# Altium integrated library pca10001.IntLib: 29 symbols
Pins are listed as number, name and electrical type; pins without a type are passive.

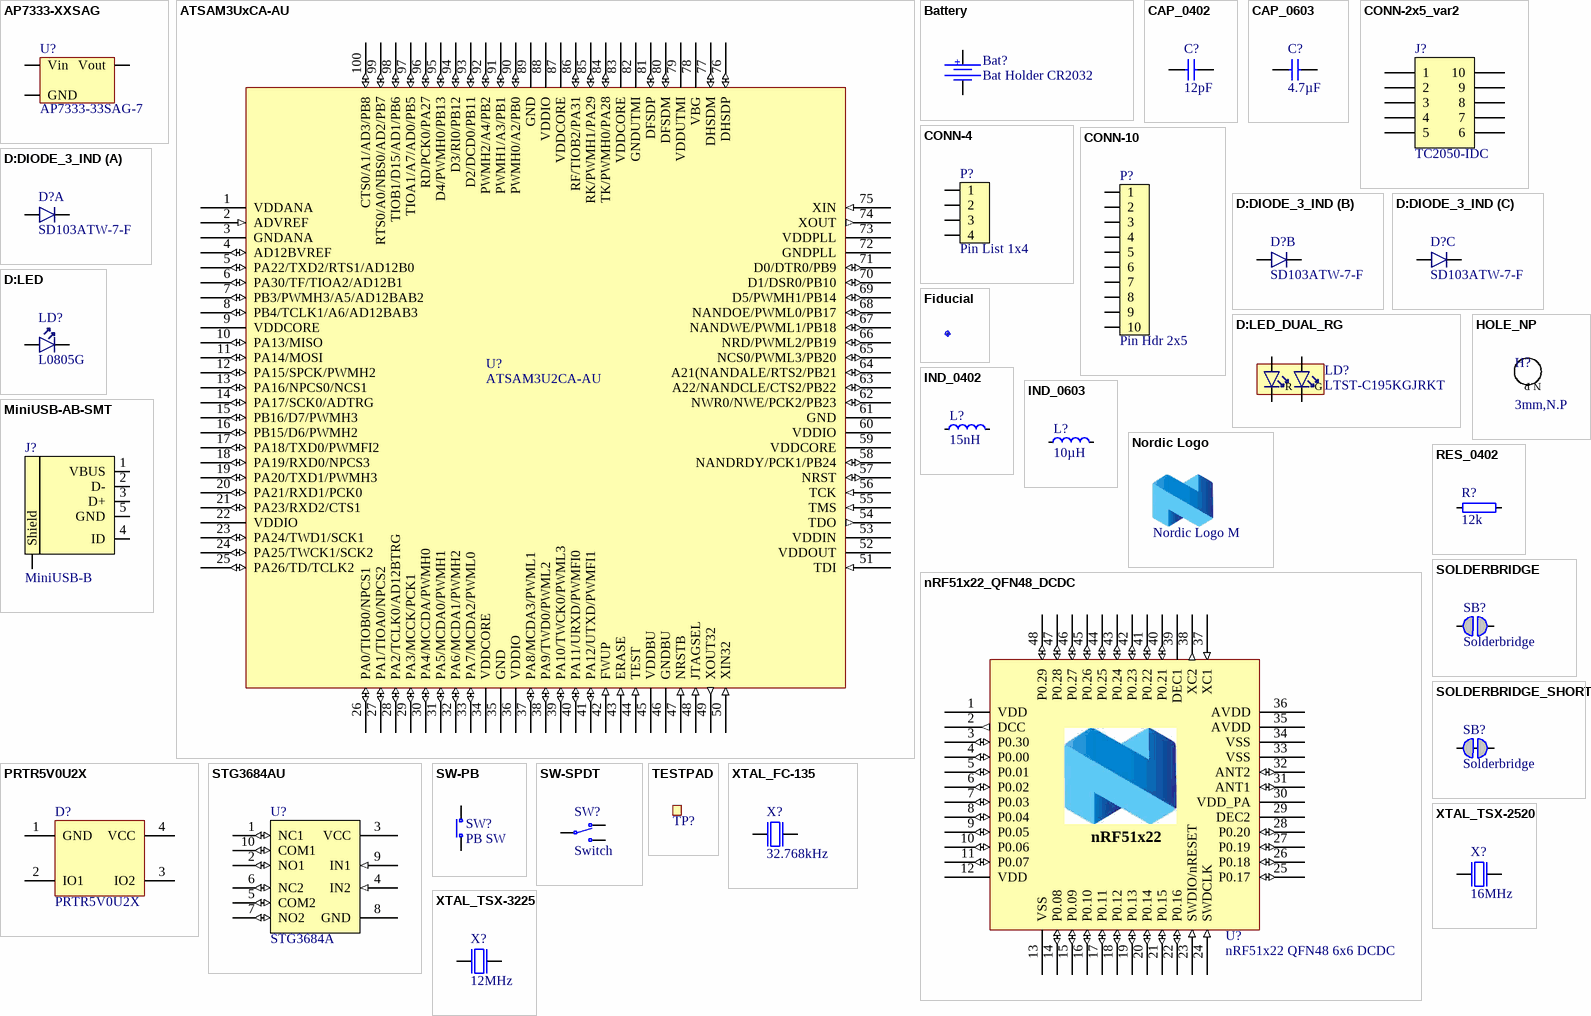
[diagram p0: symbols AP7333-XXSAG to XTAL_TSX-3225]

## AP7333-XXSAG
designator U?, comment AP7333-33SAG-7
300mA, Low Quiescent Current, Fast Transient Low Dropout Linear Regulator; Manufacturer: Diodes Incorporated; Artikkelnr Noca: 17039216
footprint SOT-23A
pins: 1 Vin, 2 Vout, 3 GND

## ATSAM3UxCA-AU
designator U?, comment ATSAM3U2CA-AU
IC MCU 32bit 128kB flash 100LQFP; Manufacturer: Atmel; 2nd source part number: 184-1662; Artikkelnr Noca: 15019073
footprint TSQFP50P1600X1600X160-100N
pins: 1 VDDANA (power), 2 ADVREF (in), 3 GNDANA (power), 4 AD12BVREF (io), 5 PA22/TXD2/RTS1/AD12B0 (io), 6 PA30/TF/TIOA2/AD12B1 (io), 7 PB3/PWMH3/A5/AD12BAB2 (io), 8 PB4/TCLK1/A6/AD12BAB3 (io), 9 VDDCORE (power), 10 PA13/MISO (io), 11 PA14/MOSI (io), 12 PA15/SPCK/PWMH2 (io), 13 PA16/NPCS0/NCS1 (io), 14 PA17/SCK0/ADTRG (io), 15 PB16/D7/PWMH3 (io), 16 PB15/D6/PWMH2 (io), 17 PA18/TXD0/PWMFI2 (io), 18 PA19/RXD0/NPCS3 (io), 19 PA20/TXD1/PWMH3 (io), 20 PA21/RXD1/PCK0 (io), 21 PA23/RXD2/CTS1 (io), 22 VDDIO (power), 23 PA24/TWD1/SCK1 (io), 24 PA25/TWCK1/SCK2 (io), 25 PA26/TD/TCLK2 (io), 26 PA0/TIOB0/NPCS1 (io), 27 PA1/TIOA0/NPCS2 (io), 28 PA2/TCLK0/AD12BTRG (io), 29 PA3/MCCK/PCK1 (io), 30 PA4/MCCDA/PWMH0 (io), 31 PA5/MCDA0/PWMH1 (io), 32 PA6/MCDA1/PWMH2 (io), 33 PA7/MCDA2/PWML0 (io), 34 VDDCORE (power), 35 GND (power), 36 VDDIO (power), 37 PA8/MCDA3/PWML1 (io), 38 PA9/TWD0/PWML2 (io), 39 PA10/TWCK0/PWML3 (io), 40 PA11/URXD/PWMFI0 (io), 41 PA12/UTXD/PWMFI1 (io), 42 FWUP (in), 43 ERASE (in), 44 TEST (in), 45 VDDBU (power), 46 GNDBU (power), 47 NRSTB (in), 48 JTAGSEL (in), 49 XOUT32 (out), 50 XIN32 (in), 51 TDI (in), 52 VDDOUT (power), 53 VDDIN (power), 54 TDO (out), 55 TMS (in), 56 TCK (in), 57 NRST (io), 58 NANDRDY/PCK1/PB24 (io), 59 VDDCORE (power), 60 VDDIO (power), 61 GND (power), 62 NWR0/NWE/PCK2/PB23 (io), 63 A22/NANDCLE/CTS2/PB22 (io), 64 A21(NANDALE/RTS2/PB21 (io), 65 NCS0/PWML3/PB20 (io), 66 NRD/PWML2/PB19 (io), 67 NANDWE/PWML1/PB18 (io), 68 NANDOE/PWML0/PB17 (io), 69 D5/PWMH1/PB14 (io), 70 D1/DSR0/PB10 (io), 71 D0/DTR0/PB9 (io), 72 GNDPLL (power), 73 VDDPLL (power), 74 XOUT (out), 75 XIN (in), 76 DHSDP (io), 77 DHSDM (io), 78 VBG (power), 79 VDDUTMI (power), 80 DFSDM (io), 81 DFSDP (io), 82 GNDUTMI (power), 83 VDDCORE (power), 84 TK/PWMH0/PA28 (io), 85 RK/PWMH1/PA29 (io), 86 RF/TIOB2/PA31 (io), 87 VDDCORE (power), 88 VDDIO (power), 89 GND (power), 90 PWMH0/A2/PB0 (io), 91 PWMH1/A3/PB1 (io), 92 PWMH2/A4/PB2 (io), 93 D2/DCD0/PB11 (io), 94 D3/RI0/PB12 (io), 95 D4/PWMH0/PB13 (io), 96 RD/PCK0/PA27 (io), 97 TIOA1/A7/AD0/PB5 (io), 98 TIOB1/D15/AD1/PB6 (io), 99 RTS0/A0/NBS0/AD2/PB7 (io), 100 CTS0/A1/AD3/PB8 (io)

## Battery
designator Bat?, comment Bat Holder CR2032
Bat Holder CR2032 SMD; Manufacturer: Keystone; Manufacturer Part Number: 3002; 2nd source part number: 69-525-27; Artikkelnr Noca: 34019038
footprint CR2032_HOLDER_SMD
pins: 1, 2

## CAP_0402
designator C?, comment 12pF
Capacitor, NP0, ±2%; Part Number: C0402-12p; Note: 50V; Artikkelnr Noca: 20029159
footprint CAPC1005X04L
pins: 1, 2

## CAP_0603
designator C?, comment 4.7µF
Capacitor, X5R, ±10%; Part Number: C0603-4µ7; Note: 6.3V; Artikkelnr Noca: 20069060
footprint CAPC1608X06L
pins: 1, 2

## CONN-2x5_var2
designator J?, comment TC2050-IDC  (no BOM)
CBL PLUG-OF-NAILS 10-PIN; Part Number: TC2050-IDC-NLFP; Manufacturer: Tag-Connect LLC; Artikkelnr Noca: N.A.
footprint TC2050-IDC-NLFP
pins: 1, 2, 3, 4, 5, 6, 7, 8, 9, 10

## CONN-4
designator P?, comment Pin List 1x4
Pin List 1x4, 2.54mm (100mil); Part Number: Pin List 1x4 SMD; Artikkelnr Noca: N.A.
footprint LIST_1x4_SMD
pins: 1, 2, 3 (power), 4 (power)

## CONN-10
designator P?, comment Pin Hdr 2x5
Pin Header 2x5, 2.54mm (100mil) SMD; Part Number: Pin Header 2x5 SMD; Manufacturer: Molex; Artikkelnr Noca: 55019194
footprint Molex 15-91-2100
pins: 1 (power), 2 (power), 3 (power), 4 (power), 5 (power), 6 (power), 7 (power), 8 (power), 9 (power), 10 (power)

## D:DIODE_3_IND
designator D?, comment SD103ATW-7-F
Surface Mount Schottky Barrier Diode Array; Manufacturer: Diodes Incorporated; 2nd source part number: 177-3507; Artikkelnr Noca: 10029109
footprint SOT-363
part A pins: 1 C1, 6 A1
part B pins: 2 C2, 5 A2
part C pins: 3 C3, 4 A3

## D:LED
designator LD?, comment L0805G
LED, SMD, 0805, GREEN; Part Number: SML-210PT; Manufacturer: ROHM; Manufacturer Part Number: SML-210PTT86; Note: 4 mcd @ 20 mA; Artikkelnr Noca: 13019123
footprint LED_0805
pins: 1 C, 2 A

## D:LED_DUAL_RG
designator LD?, comment LTST-C195KGJRKT
Avago, HSMF-A203 Bi-Color LED; Manufacturer: Lite-On Inc; 2nd source part number: 859-LTST-C195KGJRKT; Note: HSMF-A203- xxxxx GaP Red GaP Emerald Green; Artikkelnr Noca: 13019145
footprint LED_DUAL_0606
pins: 1 A2, 2 A1, 3 C2, 4 C1

## Fiducial
designator Fid?, comment Fiducial mark  (value not drawn)
Part Number: Fid-Mark; Artikkelnr Noca: N.A.
footprint Fiducial

## HOLE_NP
designator H?, comment 3mm,N.P  (no BOM)
Regular Non-Plated, 3mm hole; Part Number: Hole_3MM_NP; Manufacturer: Nordic Semiconductor; Artikkelnr Noca: N.A.
footprint HOLE_NP_3MM

## IND_0402
designator L?, comment 15nH
Inductor, 320mA, ±5%; Part Number: L0402-15n; Manufacturer: Taiyo Yuden; Manufacturer Part Number: HK100515NJ-T; 2nd source part number: 658-1328; Note: High frequency chip inductor ±10%; Artikkelnr Noca: 33029323
footprint INDC1005X04L
pins: 1, 2

## IND_0603
designator L?, comment 10µH
Inductor, 80mA, ±10%; Part Number: L0603-10µ; Manufacturer: Taiyo Yuden; Manufacturer Part Number: LBMF1608T100K; 2nd source part number: 178-6105; Note: LBMF1608T100K 10µH 80mA 0603; Artikkelnr Noca: 33029314
footprint INDC1608X06L
pins: 1, 2

## MiniUSB-AB-SMT
designator J?, comment MiniUSB-B
Hirose MiniUSB-B-SMT; Part Number: Hirose UX60SC-MB-5ST; Manufacturer Part Number: UX60SC-MB-5ST(80); 2nd source part number: 798-UX60SCMB5ST01; Artikkelnr Noca: 55029014
footprint UX60SC-MB-5ST
pins: 1 VBUS (power), 2 D- (power), 3 D+ (power), 4 ID (power), 5 GND (power), 6 Shield (power)

## Nordic Logo
designator LOGO?, comment Nordic Logo M  (no BOM)
Nordic Logo, medium size; Artikkelnr Noca: N.A.
footprint NORDIC_LOGO_M

## nRF51x22_QFN48_DCDC
designator U?, comment nRF51x22 QFN48 6x6 DCDC
*; Part Number: nRF51x22-Q48-6x6_DCDC; Manufacturer: Nordic Semiconductor; Note: nRF51x22 - QFN48 6x6 0.4mm pitch; Artikkelnr Noca: N.A.
footprint QFN40P600X600X90-48N
pins: 1 VDD (power), 2 DCC (out), 3 P0.30 (io), 4 P0.00 (io), 5 P0.01 (io), 6 P0.02 (io), 7 P0.03 (io), 8 P0.04 (io), 9 P0.05 (io), 10 P0.06 (io), 11 P0.07 (io), 12 VDD (power), 13 VSS (power), 14 P0.08 (io), 15 P0.09 (io), 16 P0.10 (io), 17 P0.11 (io), 18 P0.12 (io), 19 P0.13 (io), 20 P0.14 (io), 21 P0.15 (io), 22 P0.16 (io), 23 SWDIO/nRESET (in), 24 SWDCLK (in), 25 P0.17 (io), 26 P0.18 (io), 27 P0.19 (io), 28 P0.20 (io), 29 DEC2 (power), 30 VDD_PA (power), 31 ANT1 (io), 32 ANT2 (io), 33 VSS (power), 34 VSS (power), 35 AVDD (power), 36 AVDD (power), 37 XC1 (in), 38 XC2 (out), 39 DEC1 (power), 40 P0.21 (io), 41 P0.22 (io), 42 P0.23 (io), 43 P0.24 (io), 44 P0.25 (io), 45 P0.26 (io), 46 P0.27 (io), 47 P0.28 (io), 48 P0.29 (io), 49 (power) hidden to GND

## PRTR5V0U2X
designator D?
Ultra low capacitance double rail-to-rail ESD protection diode; Manufacturer: NXP; 2nd source part number: 152-4157; Artikkelnr Noca: 10069015
footprint SOT190P230X110-4L
pins: 1 GND, 2 IO1, 3 IO2, 4 VCC

## RES_0402
designator R?, comment 12k
Resistor, ±1%, 0.063W; Part Number: R0402-12k; Note: Chip Res 1%; Artikkelnr Noca: 27049099
footprint RESC1005X04L
pins: 1, 2

## SOLDERBRIDGE
designator SB?, comment Solderbridge  (no BOM)
Artikkelnr Noca: N.A.
footprint Solderbridge
pins: 1 0, 2 1

## SOLDERBRIDGE_SHORTED
designator SB?, comment Solderbridge  (net tie, no BOM)
Shorted Solderbridge; Part Number: Solderbridge Shorted; Artikkelnr Noca: N.A.
footprint Solderbridge_Shorted
pins: 1 0, 2 1

## STG3684AU
designator U?, comment STG3684A
Low voltage 0.5 ohm max dual SPDT switch with break-before-make; Part Number: STG3684AU; Manufacturer: STMicroelectronics; Manufacturer Part Number: STG3684AUTR; 2nd source part number: 511-STG3684AUTR; Artikkelnr Noca: N.A.
footprint QFN40P180X140X55-10N
pins: 1 NC1 (io), 2 NO1 (io), 3 VCC (power), 4 IN2 (in), 5 COM2 (io), 6 NC2 (io), 7 NO2 (io), 8 GND (power), 9 IN1 (in), 10 COM1 (io)

## SW-PB
designator SW?, comment PB SW
ALPS - SKHUALE010 - Tactile Switch, SPNO, SMD, 6.5x6.2x2.5mm; Part Number: ALPS_SKHUALE010; 2nd source part number: 688-SKHUALE010; Artikkelnr Noca: 50019001
footprint ALPS_SKHUxxx010_WO_GND
pins: 1 N.O, 2 COM

## SW-SPDT
designator SW?, comment Switch
SMD slide Switch (ON-ON); Part Number: CJS-1200TA; Manufacturer: Copal Electronics Inc; Artikkelnr Noca: N.A.
footprint CJS-120xA
pins: 1 N.C, 2 COM, 3 N.O

## TESTPAD
designator TP?, comment 1.5mm,SMD  (value not drawn)  (no BOM)
Regular Plated, 1.5mm hole; Part Number: TP_SMD_1.5MM; Manufacturer: Nordic Semiconductor; Artikkelnr Noca: N.A.
footprint TP_SMD_1.5mmX1.5mm
pins: 1

## XTAL_FC-135
designator X?, comment 32.768kHz
EPSON TOYOCOM - FC-135 32.768KHZ ±20PPM,9.0PF - CRYSTAL, SM, WATCH; Part Number: XTAL_FC-135 32.768k; 2nd source part number: 127-8037; Note: XTAL SMD 32.768kHz, 3215; Artikkelnr Noca: 22019091
footprint FC-135
pins: 1 inp, 2 out

## XTAL_TSX-2520
designator X?, comment 16MHz
XTAL SMD 2520, 16MHz, 8pF, ±15ppm; Part Number: NX2520SA-16MHZ-STD-CSW-5; Manufacturer: NDK; Note: XTAL SMD 16.000MHz; Artikkelnr Noca: 22019192
footprint BT-XTAL_2520
pins: 1 inp, 2 GND hidden to GND, 3 out, 4 GND hidden to GND

## XTAL_TSX-3225
designator X?, comment 12MHz
XTAL SMD 3225, 12MHz, 18pF, ±30ppm; Part Number: XTAL SMD 12MHz (3225); Manufacturer: TXC Corporation; Manufacturer Part Number: 7M-12.000MAAJ-T; 2nd source part number: 184-2056; Note: XTAL SMD 12.000MHz; Artikkelnr Noca: 22019166
footprint BT-XTAL_3225
pins: 1 inp, 2 GND hidden to GND, 3 out, 4 GND hidden to GND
